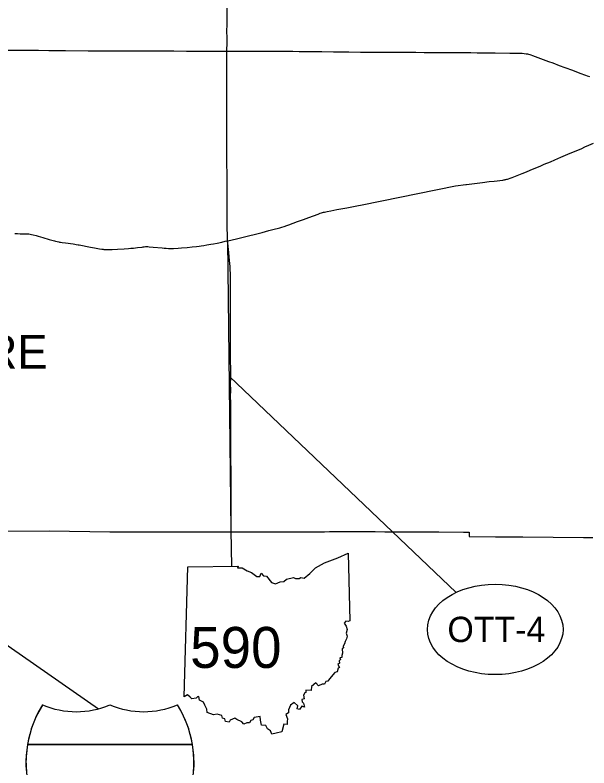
# Model space of a CAD drawing. Extents: x -82 to 873, y 0 to 440.
# Drawn here: x 201.4 to 264.9, y 99.1 to 182.3 of the extents above; entities that cross this region are included whole.
import ezdxf

# ---------------------------------------------------------------- set-up
doc = ezdxf.new("R2010")
doc.units = 0
for name, color, linetype in [('GM_P_US_Alignment', 7, 'Continuous'), ('GM_X_Corporation_Text', 7, 'Continuous'), ('GM_X_County', 7, 'Continuous'), ('GM_X_Interstate_Route', 7, 'Continuous'), ('PV_P_Text', 7, 'Continuous'), ('SH_Data', 7, 'Continuous')]:
    doc.layers.add(name, color=color, linetype=linetype)

msp = doc.modelspace()

# ---------------------------------------------------------------- linework, layer by layer
at = {"layer": 'GM_P_US_Alignment'}
msp.add_line((225.348, 125.335), (224.955, 157.375), dxfattribs=at)
at = {"layer": 'GM_X_County'}
msp.add_lwpolyline([(198.647, 125.256), (205.258, 125.298), (211.939, 125.207), (225.35, 125.188), (225.888, 125.187), (226.602, 125.186), (227.65, 125.188), (228.759, 125.187), (229.705, 125.184), (230.978, 125.187), (231.878, 125.191), (232.412, 125.195), (233.011, 125.2), (234.095, 125.209), (234.671, 125.211), (235.656, 125.213), (236.231, 125.217), (238.079, 125.22), (238.55, 125.22), (238.619, 125.224), (238.94, 125.225), (239.719, 125.223), (240.828, 125.222), (241.279, 125.219), (242.347, 125.213), (244.193, 125.2), (244.807, 125.196), (245.713, 125.188), (246.203, 125.183), (246.698, 125.183), (247.394, 125.186), (248.296, 125.187), (251.045, 125.179), (251.534, 125.173), (251.647, 125.167), (251.667, 124.665), (254.565, 124.653), (256.684, 124.635), (257.584, 124.632), (264.282, 124.586), (264.315, 124.588), (264.387, 124.587), (265.32, 124.557)], dxfattribs=at)
at = {"layer": 'GM_X_Interstate_Route'}
for points in [[(224.862, 178.301), (224.867, 178.447), (224.881, 179.155), (224.885, 179.607), (224.877, 180.716), (224.882, 181.086), (224.892, 181.702), (224.9, 182.935), (224.898, 183.634), (224.906, 184.373), (224.907, 184.95)], [(200.446, 178.437), (202.005, 178.428), (204.057, 178.418), (205.165, 178.405), (205.821, 178.387), (206.231, 178.377), (207.011, 178.375), (209.514, 178.367), (210.581, 178.363), (211.622, 178.358)], [(211.622, 178.358), (211.771, 178.356), (213.454, 178.355), (214.069, 178.355), (215.465, 178.356), (217.024, 178.352), (217.927, 178.352), (218.994, 178.346), (220.389, 178.332), (220.923, 178.325), (221.497, 178.324), (222.975, 178.311), (224.288, 178.301), (224.862, 178.301)], [(224.935, 157.355), (224.926, 157.541), (224.926, 157.623), (224.924, 157.828), (224.913, 158.896), (224.913, 159.183), (224.914, 159.593), (224.912, 160.291), (224.907, 161.318), (224.899, 162.672), (224.885, 164.807), (224.877, 165.833), (224.877, 166.326), (224.873, 166.695), (224.871, 167.557), (224.873, 169.24), (224.865, 169.978), (224.867, 172.483), (224.87, 172.812), (224.869, 174.372), (224.858, 176.301), (224.856, 177.368), (224.861, 178.148), (224.862, 178.301)], [(224.862, 178.301), (226.011, 178.302), (226.873, 178.303), (227.529, 178.301), (228.761, 178.306), (229.787, 178.307), (230.936, 178.308), (231.48, 178.305), (232.167, 178.301), (232.864, 178.292), (233.234, 178.29), (234.875, 178.27), (235.368, 178.263), (236.64, 178.252), (238.062, 178.235)], [(238.062, 178.235), (238.363, 178.231), (239.635, 178.223), (240.743, 178.219), (242.59, 178.208), (244.437, 178.195), (245.75, 178.189), (246.694, 178.186), (247.514, 178.178), (248.417, 178.174), (250.143, 178.166), (251.318, 178.159)], [(251.318, 178.159), (251.852, 178.155), (252.549, 178.149), (253.016, 178.142), (253.82, 178.135), (254.526, 178.129), (256.167, 178.113), (256.909, 178.105), (257.321, 178.093), (257.528, 178.083), (257.741, 178.062), (257.942, 178.034), (258.098, 178.006), (258.226, 177.977), (258.356, 177.944), (258.462, 177.914), (258.655, 177.852), (258.966, 177.743), (260.426, 177.192), (260.89, 177.021), (261.621, 176.746), (262.231, 176.519), (263.075, 176.205), (263.892, 175.901), (264.534, 175.662), (264.695, 175.603), (264.96, 175.504)], [(250.134, 163.431), (251.286, 163.585), (251.365, 163.595), (251.652, 163.632), (253.118, 163.815), (253.852, 163.896), (254.423, 163.964), (255.36, 164.073), (255.477, 164.09), (255.558, 164.103), (255.645, 164.12), (255.723, 164.137), (255.806, 164.155), (255.903, 164.181), (255.999, 164.21), (256.193, 164.275), (256.422, 164.363), (257.527, 164.806), (257.983, 164.991), (258.399, 165.167), (259.574, 165.653), (259.952, 165.812), (260.632, 166.1), (261.124, 166.306), (261.803, 166.597), (262.559, 166.917), (264.102, 167.575), (264.463, 167.731), (264.874, 167.911), (265.401, 168.14)], [(224.935, 157.355), (224.977, 157.363), (225.938, 157.589), (227.125, 157.879), (228.166, 158.138), (228.756, 158.285), (229.518, 158.484), (229.955, 158.597), (230.727, 158.81), (230.943, 158.872), (231.217, 158.956), (231.488, 159.046), (231.723, 159.124), (232.186, 159.291), (232.685, 159.48), (233.338, 159.726), (233.915, 159.939), (234.955, 160.322), (235.188, 160.402), (235.321, 160.444), (235.443, 160.481), (235.555, 160.511), (235.662, 160.537), (235.799, 160.566), (235.942, 160.596), (236.346, 160.679), (237.031, 160.808), (238.122, 161.004), (238.325, 161.042), (239.251, 161.215), (239.815, 161.328), (250.134, 163.431)], [(201.438, 158.169), (201.723, 158.156), (201.995, 158.145), (202.409, 158.136), (202.813, 158.127), (202.977, 158.117), (203.1, 158.103), (203.262, 158.074), (203.463, 158.025), (203.778, 157.94), (204.015, 157.868), (204.525, 157.722), (205.236, 157.513), (205.669, 157.386), (205.79, 157.35), (205.905, 157.318), (206.102, 157.272), (206.283, 157.233), (206.374, 157.217), (206.483, 157.2), (206.672, 157.172), (207.035, 157.121), (207.854, 157.01), (208.055, 156.982), (208.215, 156.959), (208.407, 156.925), (208.538, 156.898), (209.786, 156.651), (210.23, 156.572), (210.796, 156.478), (211.03, 156.444), (211.173, 156.426), (211.269, 156.415), (211.397, 156.405), (211.56, 156.396), (211.714, 156.393), (211.736, 156.392), (211.938, 156.398), (212.196, 156.411), (212.761, 156.441), (213.495, 156.482), (213.987, 156.513), (214.232, 156.528), (214.549, 156.557), (214.999, 156.612), (215.497, 156.674), (215.614, 156.689), (215.739, 156.704), (215.862, 156.715), (215.986, 156.719), (216.11, 156.717), (216.274, 156.706), (216.723, 156.655), (217.7, 156.569), (217.923, 156.55), (218.151, 156.536), (218.399, 156.526), (218.686, 156.521), (218.972, 156.525), (219.464, 156.55), (219.832, 156.575), (220.486, 156.633), (221.016, 156.688), (221.505, 156.747), (221.795, 156.78), (222.04, 156.811), (222.336, 156.854), (222.638, 156.904), (223.09, 156.984), (223.381, 157.04), (223.776, 157.116), (224.295, 157.219), (224.696, 157.304), (224.935, 157.355)], [(225.293, 138.435), (225.293, 138.675), (225.286, 139.619), (225.285, 139.989), (225.286, 141.015), (225.285, 141.426), (225.286, 142.37), (225.289, 143.232), (225.284, 144.053), (225.285, 144.586), (225.279, 144.958), (225.277, 145.079), (225.27, 145.859), (225.271, 146.803), (225.27, 147.706), (225.26, 149.553), (225.255, 150.539), (225.26, 150.867), (225.26, 151.359), (225.26, 152.427), (225.255, 153.494), (225.241, 154.397), (225.233, 154.544), (225.232, 154.562), (225.211, 154.807), (225.128, 155.583), (225.073, 156.073), (224.957, 157.092), (224.938, 157.296), (224.935, 157.355)], [(225.402, 121.4), (225.348, 125.335), (225.353, 126.114), (225.352, 127.059), (225.337, 129.522), (225.325, 130.589), (225.327, 131.205), (225.325, 131.817), (225.324, 132.313), (225.32, 132.724), (225.32, 132.97), (225.319, 133.38), (225.31, 134.653), (225.311, 135.104), (225.312, 135.925), (225.302, 136.582), (225.302, 137.198), (225.297, 137.814), (225.293, 138.347), (225.293, 138.435)], [(180.746, 126.456), (181.346, 126.038), (181.397, 126.001), (210.684, 105.646)]]:
    msp.add_lwpolyline(points, dxfattribs=at)
at = {"layer": 'PV_P_Text'}
for p, q in [((220.154, 106.955), (220.555, 121.318)), ((220.154, 106.955), (220.555, 121.318)), ((202.822, 101.701), (221.065, 101.703)), ((221.065, 101.703), (202.822, 101.701)), ((221.065, 101.703), (202.822, 101.701))]:
    msp.add_line(p, q, dxfattribs=at)
for points in [[(220.555, 121.318), (226.128, 121.412), (226.041, 121.238), (226.567, 121.202), (227.125, 120.895), (227.597, 120.701), (228.175, 120.245), (228.521, 120.25), (228.667, 120.624), (228.932, 120.335), (229.246, 120.284), (229.789, 119.596), (230.238, 119.447), (230.775, 119.683), (231.177, 119.722), (231.47, 119.955), (232.235, 120.154), (232.448, 120.035), (232.853, 120.059), (233.056, 120.147), (233.41, 120.068), (234.031, 120.59), (234.671, 121.206), (235.655, 121.787), (237.125, 122.338), (238.288, 122.83), (238.456, 115.377)], [(220.555, 121.318), (226.128, 121.412), (226.041, 121.238), (226.567, 121.202), (227.125, 120.895), (227.597, 120.701), (228.175, 120.245), (228.521, 120.25), (228.667, 120.624), (228.932, 120.335), (229.246, 120.284), (229.789, 119.596), (230.238, 119.447), (230.775, 119.683), (231.177, 119.722), (231.47, 119.955), (232.235, 120.154), (232.448, 120.035), (232.853, 120.059), (233.056, 120.147), (233.41, 120.068), (234.031, 120.59), (234.671, 121.206), (235.655, 121.787), (237.125, 122.338), (238.288, 122.83), (238.456, 115.377)], [(238.456, 115.377), (238.285, 115.272), (238.017, 115.322), (237.838, 115.112), (238.06, 114.764), (238.165, 114.395), (238.072, 113.989), (238.164, 113.654), (238.102, 113.374), (237.934, 113.095), (237.876, 112.828), (237.733, 112.548), (237.745, 112.392), (237.609, 112.267), (237.634, 111.801), (237.565, 111.543), (237.589, 111.32), (237.368, 111.261), (237.419, 111.077), (237.278, 110.935), (237.308, 110.69), (237.149, 110.534), (237.304, 110.222), (237.18, 110.122), (237.077, 109.742), (236.794, 109.665), (236.227, 108.969), (236.027, 108.706), (235.802, 108.641), (235.679, 108.371), (235.402, 108.37), (234.983, 108.183), (234.713, 108.505), (234.239, 108.117), (234.184, 107.669), (233.585, 107.683), (233.608, 107.457), (233.474, 107.391), (233.352, 107.164), (233.423, 106.761), (233.143, 106.658), (233.177, 106.424), (233.356, 106.281), (233.436, 105.834), (233.138, 105.924), (232.894, 105.547), (232.642, 105.636), (232.725, 105.955), (232.3, 106.339), (231.898, 106.032), (231.689, 105.54), (231.687, 105.21), (231.387, 105.01), (231.579, 104.543), (231.544, 104.221), (231.55, 103.915), (231.176, 103.926), (230.95, 103.101)], [(238.456, 115.377), (238.285, 115.272), (238.017, 115.322), (237.838, 115.112), (238.06, 114.764), (238.165, 114.395), (238.072, 113.989), (238.164, 113.654), (238.102, 113.374), (237.934, 113.095), (237.876, 112.828), (237.733, 112.548), (237.745, 112.392), (237.609, 112.267), (237.634, 111.801), (237.565, 111.543), (237.589, 111.32), (237.368, 111.261), (237.419, 111.077), (237.278, 110.935), (237.308, 110.69), (237.149, 110.534), (237.304, 110.222), (237.18, 110.122), (237.077, 109.742), (236.794, 109.665), (236.227, 108.969), (236.027, 108.706), (235.802, 108.641), (235.679, 108.371), (235.402, 108.37), (234.983, 108.183), (234.713, 108.505), (234.239, 108.117), (234.184, 107.669), (233.585, 107.683), (233.608, 107.457), (233.474, 107.391), (233.352, 107.164), (233.423, 106.761), (233.143, 106.658), (233.177, 106.424), (233.356, 106.281), (233.436, 105.834), (233.138, 105.924), (232.894, 105.547), (232.642, 105.636), (232.725, 105.955), (232.3, 106.339), (231.898, 106.032), (231.689, 105.54), (231.687, 105.21), (231.387, 105.01), (231.579, 104.543), (231.544, 104.221), (231.55, 103.915), (231.176, 103.926), (230.95, 103.101)], [(230.95, 103.101), (230.299, 102.944), (229.848, 102.849), (229.689, 103.224), (229.366, 103.421), (229.156, 103.799), (228.692, 103.85), (228.582, 104.368), (228.53, 104.788), (227.897, 104.684), (227.723, 104.427), (227.498, 104.358), (227.367, 104.099), (227.061, 104.078), (226.732, 103.956), (226.517, 104.209), (225.978, 104.464), (225.736, 104.596), (225.23, 104.391), (225.121, 104.15), (224.718, 104.256), (224.624, 104.526), (224.38, 104.607), (224.326, 104.893), (223.805, 105.045), (223.406, 104.985), (222.702, 105.215), (222.659, 105.591), (222.42, 106.05), (222.295, 106.368), (221.85, 106.611), (221.76, 106.99), (221.618, 106.979), (221.488, 106.825), (220.994, 106.754), (220.796, 106.909), (220.52, 107.173), (220.154, 106.955)], [(230.95, 103.101), (230.299, 102.944), (229.848, 102.849), (229.689, 103.224), (229.366, 103.421), (229.156, 103.799), (228.692, 103.85), (228.582, 104.368), (228.53, 104.788), (227.897, 104.684), (227.723, 104.427), (227.498, 104.358), (227.367, 104.099), (227.061, 104.078), (226.732, 103.956), (226.517, 104.209), (225.978, 104.464), (225.736, 104.596), (225.23, 104.391), (225.121, 104.15), (224.718, 104.256), (224.624, 104.526), (224.38, 104.607), (224.326, 104.893), (223.805, 105.045), (223.406, 104.985), (222.702, 105.215), (222.659, 105.591), (222.42, 106.05), (222.295, 106.368), (221.85, 106.611), (221.76, 106.99), (221.618, 106.979), (221.488, 106.825), (220.994, 106.754), (220.796, 106.909), (220.52, 107.173), (220.154, 106.955)]]:
    msp.add_lwpolyline(points, dxfattribs=at)
for centre, radius, start, end in [((214.642, 99.693), 11.99, 147.82661, 256.99913), ((213.893, 99.901), 11.216, 146.65897, 170.76399), ((208.218, 114.89), 9.567, 247.08982, 292.91553), ((208.218, 114.89), 9.567, 247.08982, 292.91553), ((215.667, 114.892), 9.569, 247.09662, 292.91336), ((215.667, 114.892), 9.569, 247.09662, 292.91336), ((209.246, 99.693), 11.989, 283.01154, 32.18368), ((209.246, 99.692), 11.99, 9.65253, 32.18402), ((214.642, 99.693), 11.989, 170.35636, 257.0017), ((209.27, 99.688), 11.966, 282.77165, 9.69483)]:
    msp.add_arc(centre, radius, start, end, dxfattribs=at)
at = {"layer": 'SH_Data'}
msp.add_line((250.226, 118.508), (225.139, 142.347), dxfattribs=at)
msp.add_ellipse((254.534, 114.415), major_axis=(7.5, 0), ratio=0.666667, dxfattribs=at)

# ---------------------------------------------------------------- texts
at = {"layer": 'GM_X_Corporation_Text'}
msp.add_text('ELMORE', height=3.75, rotation=0.00501, dxfattribs=at).set_placement((183.873, 143.21))
at = {"layer": 'PV_P_Text'}
msp.add_text('590', height=4.5281, rotation=0.005, dxfattribs=at).set_placement((220.808, 110.158))
at = {"layer": 'SH_Data'}
msp.add_text('OTT-4', height=2.8, dxfattribs=at).set_placement((249.253, 113.015))

doc.saveas('drawing.dxf')
